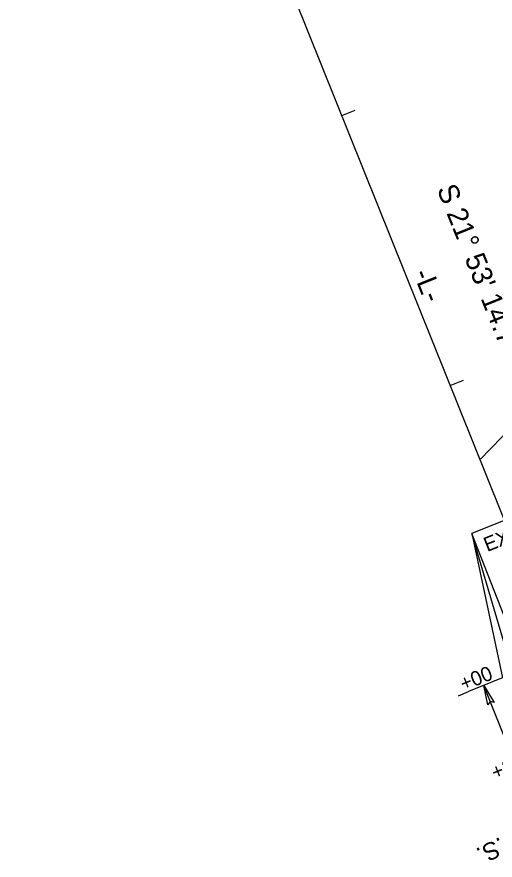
# Model space of a CAD drawing. Extents: x 1702862 to 1704514, y 793768 to 796215.
# Drawn here: x 1702863.3 to 1703028, y 795564.6 to 795854.5 of the extents above; entities that cross this region are included whole.
import ezdxf

# ---------------------------------------------------------------- set-up
doc = ezdxf.new("R2010")
doc.units = 0
for name, color, linetype in [('Prop Dimension', 7, 'Continuous'), ('Prop DSN Text', 7, 'Continuous'), ('Prop EOT', 7, 'Continuous'), ('Prop Horizontal Alignment', 7, 'Continuous'), ('Prop Horizontal Alignment Direction Label', 7, 'Continuous'), ('Prop Horizontal Alignment Tick Small', 7, 'Continuous'), ('Prop Paved Shoulder', 7, 'Continuous'), ('Prop SS Fill Line', 7, 'Continuous'), ('Prop Superelevation Label', 7, 'Continuous')]:
    doc.layers.add(name, color=color, linetype=linetype)

msp = doc.modelspace()

# ---------------------------------------------------------------- linework, layer by layer
at = {"layer": 'Prop Dimension'}
msp.add_line((1703015.37, 795621.07), (1703018.79, 795622.56), dxfattribs=at)
at = {"layer": 'Prop EOT'}
for p in [(1703031.09, 795681.38), (1703034.25, 795640.31)]:
    msp.add_line(p, (1703019.95, 795676.91), dxfattribs=at)
at = {"layer": 'Prop Horizontal Alignment'}
msp.add_line((1702863.33, 796098.94), (1703053.56, 795625.43), dxfattribs=at)
at = {"layer": 'Prop Horizontal Alignment Direction Label'}
msp.add_lwpolyline([(1703037.89, 795730.02), (1703041.67, 795721.65), (1703022.72, 795702.21)], dxfattribs=at)
at = {"layer": 'Prop Horizontal Alignment Tick Small'}
for p, q in [((1702975.17, 795820.57), (1702979.81, 795822.43)), ((1703012.45, 795727.78), (1703017.09, 795729.64))]:
    msp.add_line(p, q, dxfattribs=at)
at = {"layer": 'Prop Paved Shoulder'}
msp.add_line((1703034.17, 795628.74), (1703019.95, 795676.91), dxfattribs=at)
at = {"layer": 'Prop SS Fill Line'}
msp.add_line((1703019.95, 795676.91), (1703030.46, 795627.25), dxfattribs=at)
at = {"layer": 'Prop Superelevation Label'}
for p, q in [((1703035.53, 795629.28), (1703018.79, 795622.56)), ((1703033.5, 795601.08), (1703024.01, 795624.65))]:
    msp.add_line(p, q, dxfattribs=at)
msp.add_lwpolyline([(1703025.45, 795617.96), (1703024.01, 795624.65), (1703027.66, 795618.8), (1703026.22, 795619.16)], close=True, dxfattribs=at)

# ---------------------------------------------------------------- texts
at = {"layer": 'Prop Dimension'}
msp.add_text('P.S.', height=6, rotation=206.2405, dxfattribs=at).set_placement((1703034.48, 795575.02))
at = {"layer": 'Prop DSN Text'}
msp.add_text('EXIST.', height=5, rotation=21.7746, dxfattribs=at).set_placement((1703025.23, 795670.49))
at = {"layer": 'Prop Horizontal Alignment Direction Label'}
for s, p in [('S 21%%d 53\' 14.7" E', (1703007.81, 795795.28)), ('-L-', (1702999.63, 795766.3))]:
    msp.add_text(s, height=7, rotation=291.8874, dxfattribs=at).set_placement(p)
at = {"layer": 'Prop Superelevation Label'}
for s, p in [('+00', (1703017.06, 795622.68)), ('+25.00', (1703027.89, 795592.17))]:
    msp.add_text(s, height=5, rotation=21.8881, dxfattribs=at).set_placement(p)

doc.saveas('drawing.dxf')
